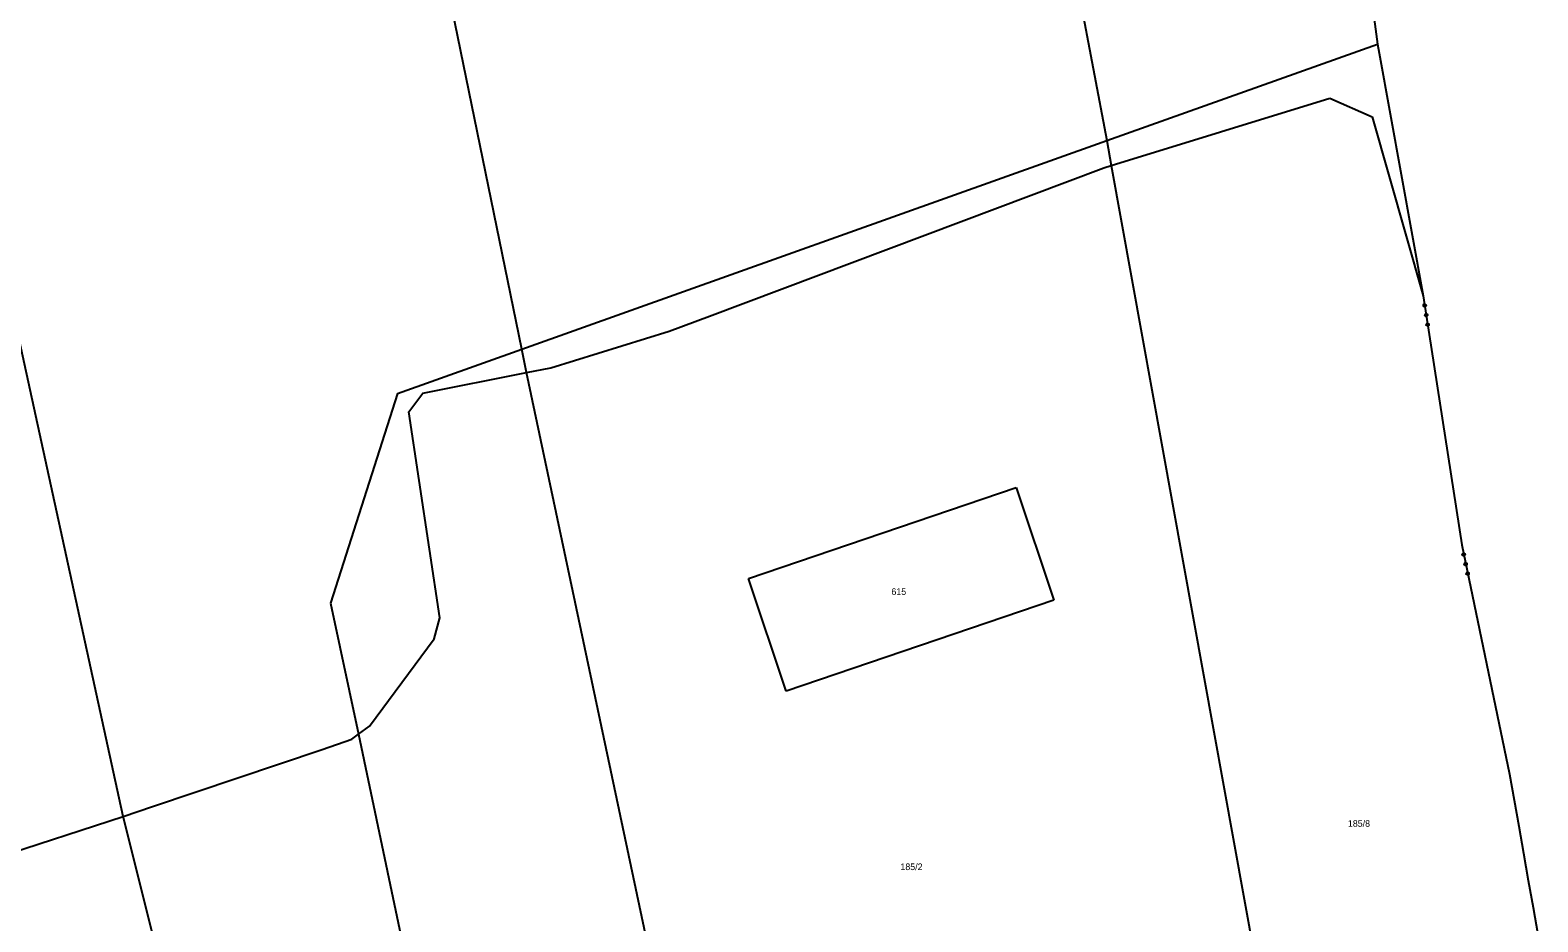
# Model space of a CAD drawing. Extents: x -757994 to -755874, y -1047691 to -1046119.
# Drawn here: x -756185.8 to -755991.8, y -1046423.9 to -1046309.2 of the extents above; entities that cross this region are included whole.
import ezdxf

# ---------------------------------------------------------------- set-up
doc = ezdxf.new("R2010")
doc.units = 0
doc.layers.add('katastrální mapa', color=7, linetype='Continuous')

msp = doc.modelspace()

# ---------------------------------------------------------------- linework, layer by layer
at = {"layer": 'katastrální mapa'}
for p, q in [((-756122.56, -1046350.25), (-756147.01, -1046231.15)), ((-756173.88, -1046410.35), (-756209, -1046249.32)), ((-756015.64, -1046287.45), (-756012.44, -1046311.02)), ((-756052.79, -1046294.45), (-756047.28, -1046323.43)), ((-756047.28, -1046323.43), (-756012.44, -1046311.02)), ((-756012.44, -1046311.02), (-756012.23, -1046312.19)), ((-756012.23, -1046312.19), (-756006.57, -1046343.39)), ((-756046.72, -1046326.63), (-756018.6, -1046317.95)), ((-756018.6, -1046317.95), (-756013.14, -1046320.35)), ((-756013.14, -1046320.35), (-756006.57, -1046343.39)), ((-756122.56, -1046350.25), (-756047.28, -1046323.43)), ((-756047.28, -1046323.43), (-756046.72, -1046326.63)), ((-756098.4, -1046346), (-756047.66, -1046326.92)), ((-756047.66, -1046326.92), (-756046.72, -1046326.63)), ((-756046.72, -1046326.63), (-756013.4, -1046510.33)), ((-756006.57, -1046343.39), (-756001.62, -1046375.44)), ((-756103.59, -1046347.92), (-756098.4, -1046346)), ((-756118.84, -1046352.66), (-756103.59, -1046347.92)), ((-756138.55, -1046355.94), (-756122.56, -1046350.25)), ((-756121.95, -1046353.27), (-756122.56, -1046350.25)), ((-756135.31, -1046355.91), (-756121.95, -1046353.27)), ((-756121.95, -1046353.27), (-756118.84, -1046352.66)), ((-756102.91, -1046443.07), (-756121.95, -1046353.27)), ((-756138.55, -1046355.94), (-756147.19, -1046382.91)), ((-756137.09, -1046358.32), (-756135.31, -1046355.91)), ((-756133.13, -1046384.81), (-756137.09, -1046358.32)), ((-756093.39, -1046379.73), (-756058.93, -1046368.05)), ((-756058.93, -1046368.05), (-756054.09, -1046382.54)), ((-756001.62, -1046375.44), (-755995.46, -1046404.9)), ((-756088.56, -1046394.23), (-756093.39, -1046379.73)), ((-756147.19, -1046382.91), (-756143.56, -1046399.77)), ((-756054.09, -1046382.54), (-756088.56, -1046394.23)), ((-756133.85, -1046387.49), (-756133.13, -1046384.81)), ((-756142.17, -1046398.74), (-756133.85, -1046387.49)), ((-756143.56, -1046399.77), (-756142.17, -1046398.74)), ((-756148.26, -1046401.74), (-756144.43, -1046400.42)), ((-756144.43, -1046400.42), (-756143.56, -1046399.77)), ((-756143.56, -1046399.77), (-756123.17, -1046497.22)), ((-756170.07, -1046409.07), (-756148.26, -1046401.74)), ((-755995.46, -1046404.9), (-755994.28, -1046411.61)), ((-756212.72, -1046423), (-756173.88, -1046410.35)), ((-756173.88, -1046410.35), (-756170.07, -1046409.07)), ((-756150.09, -1046504.58), (-756173.88, -1046410.35)), ((-755994.28, -1046411.61), (-755993.66, -1046415.09)), ((-755993.66, -1046415.09), (-755993.05, -1046418.58)), ((-755993.05, -1046418.58), (-755992.43, -1046422.07)), ((-755992.43, -1046422.07), (-755991.82, -1046425.56))]:
    msp.add_line(p, q, dxfattribs=at)
for points in [[(-756006.21, -1046344.67), (-756006.29, -1046344.77), (-756006.42, -1046344.79), (-756006.53, -1046344.71), (-756006.55, -1046344.58), (-756006.47, -1046344.47), (-756006.34, -1046344.45), (-756006.23, -1046344.53), (-756006.21, -1046344.67), (-756006.23, -1046344.67), (-756006.25, -1046344.55), (-756006.29, -1046344.52), (-756006.26, -1046344.72), (-756006.3, -1046344.75), (-756006.34, -1046344.49), (-756006.38, -1046344.49), (-756006.34, -1046344.76), (-756006.38, -1046344.77), (-756006.42, -1046344.5), (-756006.46, -1046344.51), (-756006.42, -1046344.77), (-756006.46, -1046344.75), (-756006.49, -1046344.54), (-756006.53, -1046344.58), (-756006.51, -1046344.72)], [(-756006.02, -1046345.91), (-756006.1, -1046346.01), (-756006.23, -1046346.03), (-756006.34, -1046345.96), (-756006.36, -1046345.82), (-756006.28, -1046345.71), (-756006.15, -1046345.69), (-756006.04, -1046345.77), (-756006.02, -1046345.91), (-756006.04, -1046345.9), (-756006.06, -1046345.78), (-756006.1, -1046345.75), (-756006.07, -1046345.95), (-756006.11, -1046345.99), (-756006.15, -1046345.72), (-756006.19, -1046345.72), (-756006.15, -1046346), (-756006.19, -1046346.01), (-756006.23, -1046345.73), (-756006.27, -1046345.74), (-756006.23, -1046346.01), (-756006.27, -1046345.98), (-756006.3, -1046345.78), (-756006.34, -1046345.83), (-756006.32, -1046345.95)], [(-756005.83, -1046347.15), (-756005.91, -1046347.25), (-756006.04, -1046347.27), (-756006.15, -1046347.2), (-756006.17, -1046347.06), (-756006.09, -1046346.95), (-756005.96, -1046346.93), (-756005.85, -1046347.01), (-756005.83, -1046347.15), (-756005.85, -1046347.13), (-756005.87, -1046347.01), (-756005.91, -1046346.99), (-756005.88, -1046347.17), (-756005.92, -1046347.22), (-756005.96, -1046346.96), (-756006, -1046346.97), (-756005.96, -1046347.23), (-756006, -1046347.23), (-756006.04, -1046346.98), (-756006.08, -1046346.98), (-756006.04, -1046347.23), (-756006.08, -1046347.22), (-756006.11, -1046347.02), (-756006.15, -1046347.05), (-756006.13, -1046347.17)], [(-756001.19, -1046376.69), (-756001.27, -1046376.81), (-756001.4, -1046376.83), (-756001.51, -1046376.76), (-756001.54, -1046376.63), (-756001.47, -1046376.52), (-756001.33, -1046376.49), (-756001.22, -1046376.56), (-756001.19, -1046376.69), (-756001.21, -1046376.7), (-756001.24, -1046376.59), (-756001.29, -1046376.56), (-756001.24, -1046376.75), (-756001.28, -1046376.79), (-756001.33, -1046376.52), (-756001.37, -1046376.53), (-756001.32, -1046376.79), (-756001.36, -1046376.8), (-756001.41, -1046376.55), (-756001.45, -1046376.55), (-756001.39, -1046376.81), (-756001.44, -1046376.8), (-756001.48, -1046376.59), (-756001.52, -1046376.63), (-756001.49, -1046376.77)], [(-756000.94, -1046377.92), (-756001.01, -1046378.04), (-756001.14, -1046378.06), (-756001.26, -1046377.99), (-756001.28, -1046377.86), (-756001.21, -1046377.74), (-756001.08, -1046377.72), (-756000.97, -1046377.79), (-756000.94, -1046377.92), (-756000.96, -1046377.92), (-756000.98, -1046377.8), (-756001.03, -1046377.77), (-756000.99, -1046377.97), (-756001.02, -1046378.02), (-756001.08, -1046377.74), (-756001.12, -1046377.75), (-756001.06, -1046378.02), (-756001.1, -1046378.03), (-756001.16, -1046377.76), (-756001.19, -1046377.77), (-756001.14, -1046378.04), (-756001.18, -1046378.01), (-756001.23, -1046377.81), (-756001.26, -1046377.86), (-756001.23, -1046377.98)], [(-756000.68, -1046379.15), (-756000.75, -1046379.26), (-756000.89, -1046379.29), (-756001, -1046379.22), (-756001.03, -1046379.09), (-756000.95, -1046378.97), (-756000.82, -1046378.95), (-756000.71, -1046379.02), (-756000.68, -1046379.15), (-756000.7, -1046379.14), (-756000.73, -1046379.02), (-756000.77, -1046379), (-756000.73, -1046379.18), (-756000.77, -1046379.23), (-756000.82, -1046378.98), (-756000.86, -1046378.98), (-756000.8, -1046379.24), (-756000.84, -1046379.25), (-756000.9, -1046378.99), (-756000.94, -1046379), (-756000.88, -1046379.25), (-756000.93, -1046379.24), (-756000.97, -1046379.04), (-756001, -1046379.07), (-756000.98, -1046379.19)]]:
    msp.add_lwpolyline(points, dxfattribs=at)

# ---------------------------------------------------------------- texts
for s, p in [('615', (-756075, -1046381.86)), ('185/8', (-756016.26, -1046411.69)), ('185/2', (-756073.84, -1046417.26))]:
    msp.add_text(s, height=0.85, dxfattribs=at).set_placement(p)

doc.saveas('drawing.dxf')
